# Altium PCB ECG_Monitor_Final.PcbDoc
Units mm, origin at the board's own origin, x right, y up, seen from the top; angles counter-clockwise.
Board outline 95 x 87 mm, 2 copper layers (Top Layer, Bottom Layer); 59 components, 41 nets, 158 pads, 2 vias.
Unrouted connection lines stored in the file: 17.
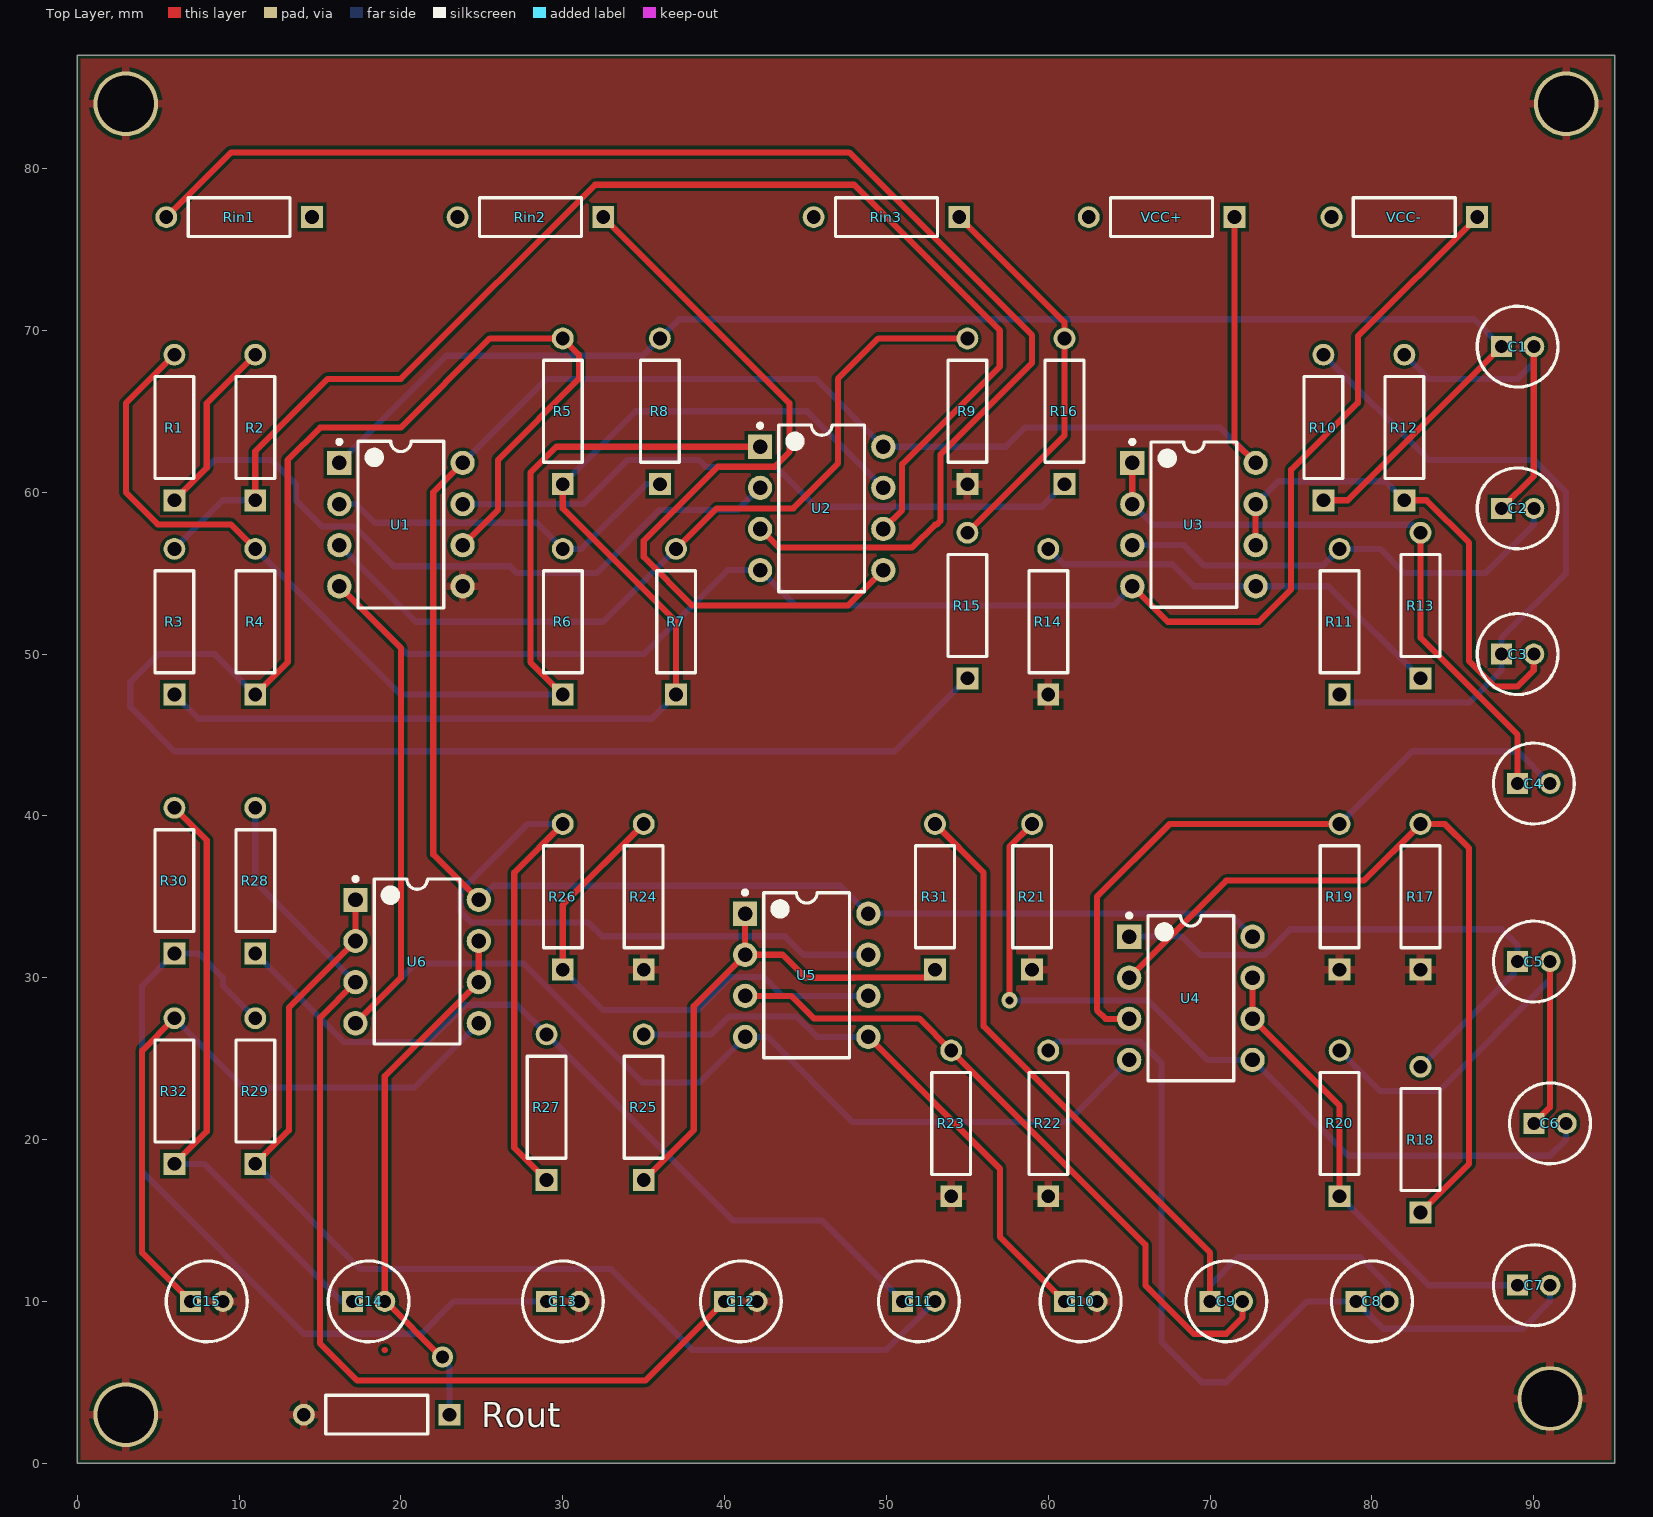
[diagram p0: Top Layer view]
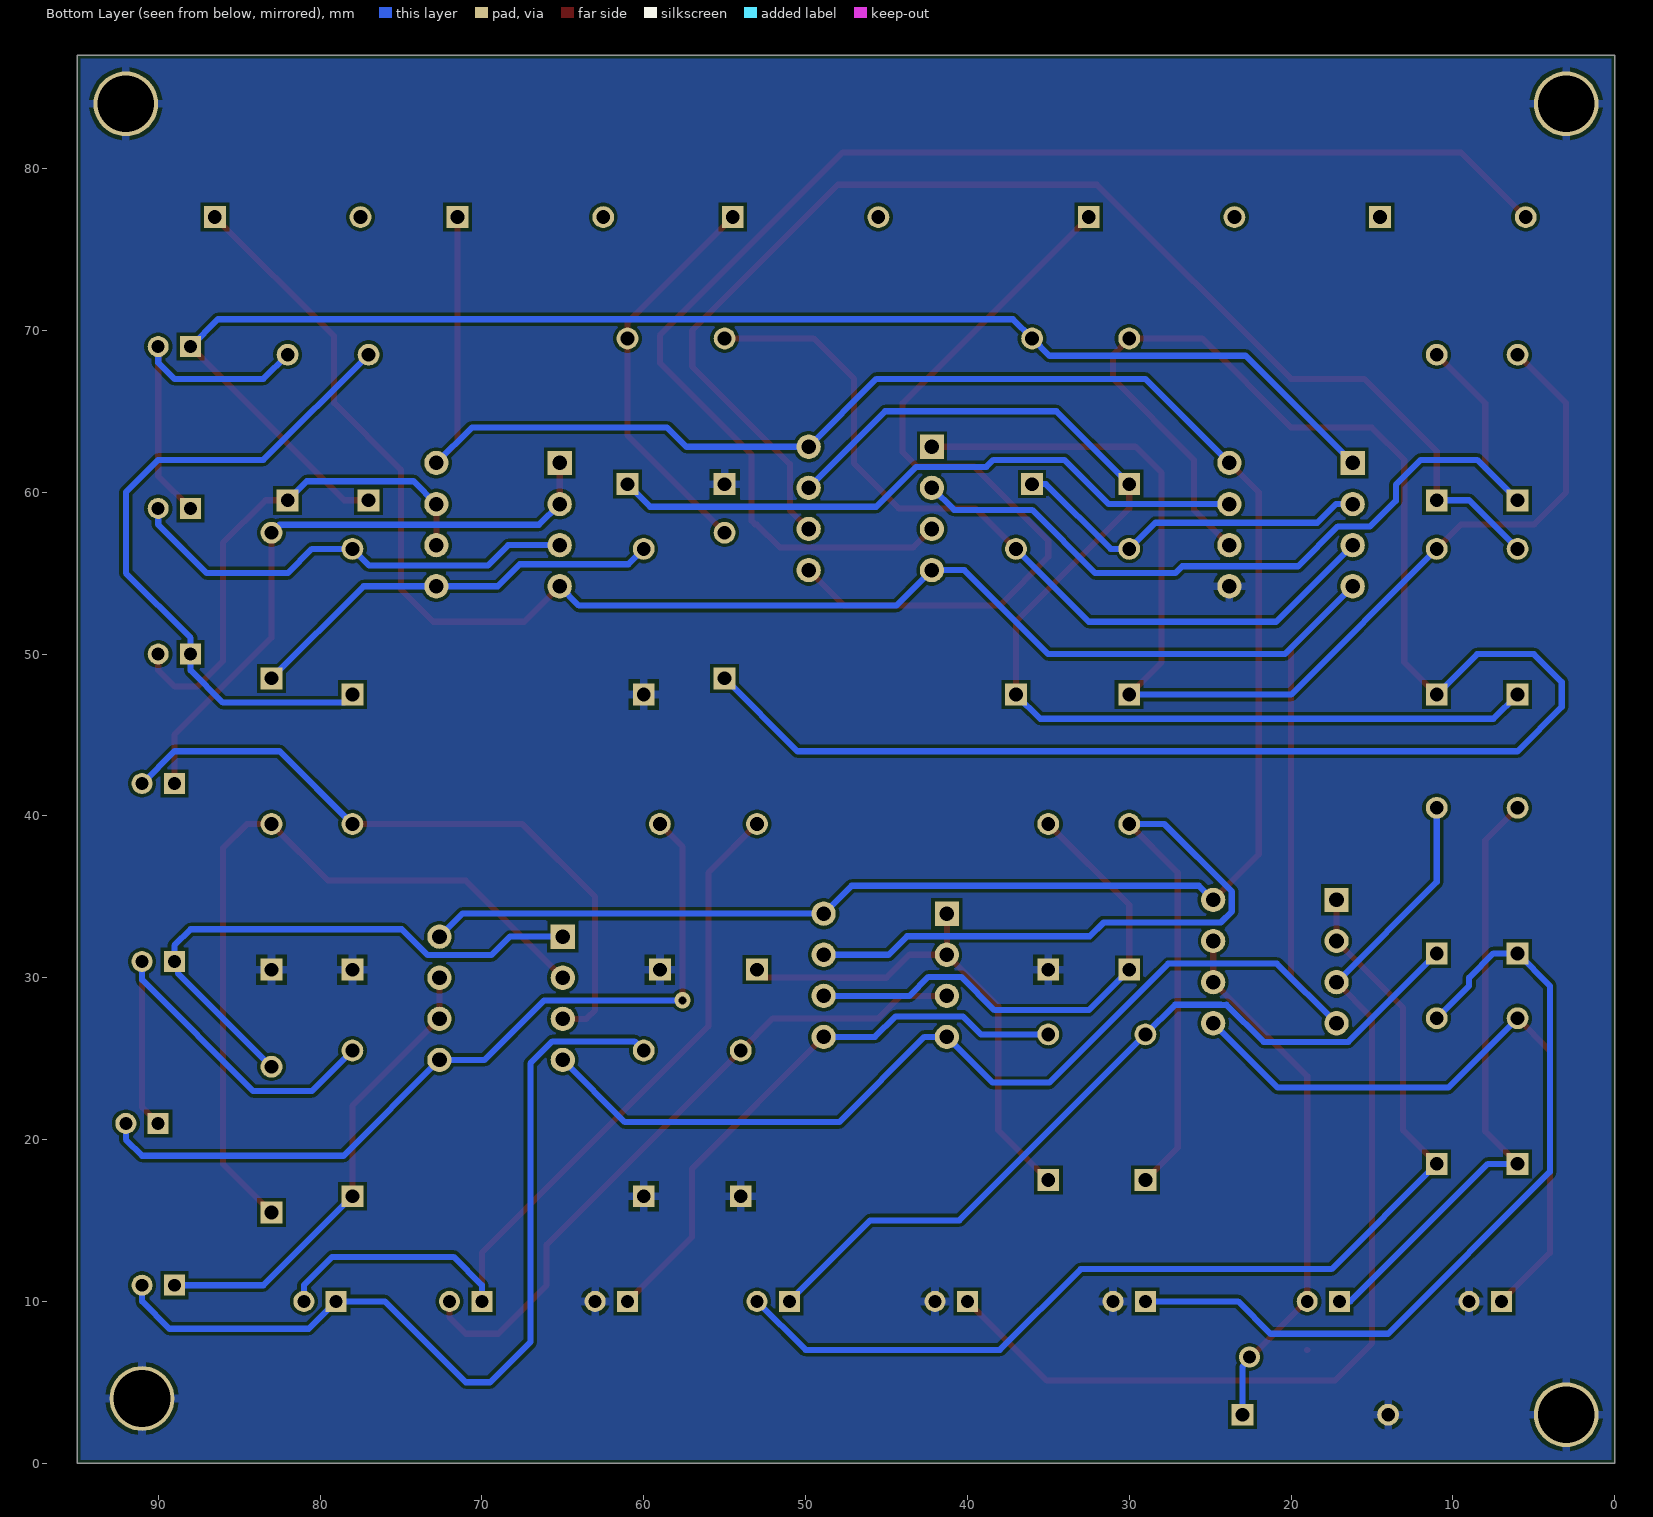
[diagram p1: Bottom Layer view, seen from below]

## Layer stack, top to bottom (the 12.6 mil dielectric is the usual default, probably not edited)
Top Solder: solder mask 0.0102, Solder Resist, Dk 3.5
Top Layer: signal copper 0.0356
Dielectric 1: dielectric 0.32, FR-4, Dk 4.8
Bottom Layer: signal copper 0.0356
Bottom Solder: solder mask 0.0102, Solder Resist, Dk 3.5

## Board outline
0,0 95,0 95,87 0,87

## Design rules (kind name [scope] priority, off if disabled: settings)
BoardOutlineClearance [All] p1: gap=0.2 ignorepadtopadclearanceinfootprint=FALSE except(0.4: Arc-SplitBarrior Arc-SplitContinuation Track-SplitBarrior Track-SplitContinuation SMDPad-SplitBarrior SMDPad-SplitContinuation THPad-SplitBarrior THPad-SplitContinuation Via-SplitBarrior Via-SplitContinuation Fill-SplitBarrior Fill-SplitContinuation Poly-SplitBarrior Poly-SplitContinuation Region-SplitBarrior Region-SplitContinuation Text-SplitBarrior Text-SplitContinuation)
Clearance "Clearance Bottom Layer" [OnLayer('Bottom Layer')] p1: gap=0.203 ignorepadtopadclearanceinfootprint=TRUE except(0.254: Arc-Text Track-Text SMDPad-Text THPad-Text Via-Text Fill-Text Poly-Text Region-Text Text-Text)
Clearance "Clearance Top Layer" [OnLayer('Top Layer')] p2: gap=0.203 ignorepadtopadclearanceinfootprint=TRUE except(0.254: Arc-Text Track-Text SMDPad-Text THPad-Text Via-Text Fill-Text Poly-Text Region-Text Text-Text)
Clearance [All] p3: gap=0.2 ignorepadtopadclearanceinfootprint=FALSE except(0.089: Arc-Arc Arc-Track Arc-SMDPad Track-Track Track-SMDPad SMDPad-SMDPad; 0.127: Arc-Via Track-Via SMDPad-Via THPad-Via Via-Via; 0.254: Arc-Text Track-Text SMDPad-Text THPad-Text Via-Text Fill-Text Poly-Text Region-Text Text-Text)
HoleSize [All] p1: absolutevalues=TRUE maxlimit=6.3 minlimit=0.2 maxpercent=80.000 minpercent=20.000
MinimumAnnularRing [All] p1: minimumring=0.076
MinimumSolderMaskSliver [All] p1: minsoldermaskwidth=0.1
PolygonConnect PolygonConnect_1 [All] p1: thpad.connectstyle=Relief thpad.reliefconductorwidth=0.508 thpad.reliefentries=4 thpad.polygonreliefangle="90 Angle" thpad.airgapwidth=0.254 smdpad.connectstyle=Relief smdpad.reliefconductorwidth=0.508 smdpad.reliefentries=4 smdpad.polygonreliefangle="90 Angle" smdpad.airgapwidth=0.254 via.connectstyle=Direct via.reliefconductorwidth=0.508 via.reliefentries=4 via.polygonreliefangle="90 Angle" via.airgapwidth=0.254
RoutingCorners [All] p1: cornerstyle=Round minsetback=2.54 maxsetback=2.54
RoutingVias [All] p1: holewidth=0.5 width=1 viastyle="Through Hole" minholewidth=0.2 minwidth=0.45 maxholewidth=1 maxwidth=2
SilkToSilkClearance [All] p1: silktosilkclearance=0.1
SilkToSolderMaskClearance [IsPad] p1: minsilkscreentomaskgap=0.1 clearancetoexposedcopper=TRUE
SolderMaskExpansion [All] p1: expansion=0.102 istentingtop=FALSE
Width [All] p1: maxlimit=2.54 minlimit=0.089 preferedwidth=0.381
25 further rules are at their usual default settings.

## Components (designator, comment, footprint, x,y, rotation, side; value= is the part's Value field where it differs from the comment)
C1 "ECA1HM100" CAPPR55-200-1100X500X1200 89,69 r0 top
C2 "ECA1HM100" CAPPR55-200-1100X500X1200 89,59 r0 top
C3 "ECA1HM100" CAPPR55-200-1100X500X1200 89,50 r0 top
C4 "ECA1HM100" CAPPR55-200-1100X500X1200 90,42 r0 top
C5 "ECA1HM100" CAPPR55-200-1100X500X1200 90,31 r0 top
C6 "ECA1HM100" CAPPR55-200-1100X500X1200 91,21 r0 top
C7 "ECA1HM100" CAPPR55-200-1100X500X1200 90,11 r0 top
C8 "ECA1HM100" CAPPR55-200-1100X500X1200 80,10 r0 top
C9 "ECA1HM100" CAPPR55-200-1100X500X1200 71,10 r0 top
C10 "ECA1HM100" CAPPR55-200-1100X500X1200 62,10 r0 top
C11 "ECA1HM100" CAPPR55-200-1100X500X1200 52,10 r0 top
C12 "ECA1HM100" CAPPR55-200-1100X500X1200 41,10 r0 top
C13 "ECA1HM100" CAPPR55-200-1100X500X1200 30,10 r0 top
C14 "ECA1HM100" CAPPR55-200-1100X500X1200 18,10 r0 top
C15 "ECA1HM100" CAPPR55-200-1100X500X1200 8,10 r0 top
R1 "" RESA60-630X240 6,64 r90 top
R2 "" RESA60-630X240 11,64 r90 top
R3 "" RESA60-630X240 6,52 r90 top
R4 "" RESA60-630X240 11,52 r90 top
R5 "" RESA60-630X240 30,65 r90 top
R6 "" RESA60-630X240 30,52 r90 top
R7 "" RESA60-630X240 37,52 r90 top
R8 "" RESA60-630X240 36,65 r90 top
R9 "" RESA60-630X240 55,65 r90 top
R10 "" RESA60-630X240 77,64 r90 top
R11 "" RESA60-630X240 78,52 r90 top
R12 "" RESA60-630X240 82,64 r90 top
R13 "" RESA60-630X240 83,53 r90 top
R14 "" RESA60-630X240 60,52 r90 top
R15 "" RESA60-630X240 55,53 r90 top
R16 "" RESA60-630X240 61,65 r90 top
R17 "" RESA60-630X240 83,35 r90 top
R18 "" RESA60-630X240 83,20 r90 top
R19 "" RESA60-630X240 78,35 r90 top
R20 "" RESA60-630X240 78,21 r90 top
R21 "" RESA60-630X240 59,35 r90 top
R22 "" RESA60-630X240 60,21 r90 top
R23 "" RESA60-630X240 54,21 r90 top
R24 "" RESA60-630X240 35,35 r90 top
R25 "" RESA60-630X240 35,22 r90 top
R26 "" RESA60-630X240 30,35 r90 top
R27 "" RESA60-630X240 29,22 r90 top
R28 "" RESA60-630X240 11,36 r90 top
R29 "" RESA60-630X240 11,23 r90 top
R30 "" RESA60-630X240 6,36 r90 top
R31 "" RESA60-630X240 53,35 r90 top
R32 "" RESA60-630X240 6,23 r90 top
Rin1 "" RESA60-630X240 10,77 r180 top
Rin2 "" RESA60-630X240 28,77 r180 top
Rin3 "" RESA60-630X240 50,77 r180 top
Rout "" RESA60-630X240 18.5,3 r180 top
U1 "LM4562NA" N08E 20,58 r0 top
U2 "LM4562NA" N08E 46,59 r0 top
U3 "TL072CP" P0008A 69,58 r0 top
U4 "TL072CP" P0008A 68.81,28.73 r0 top
U5 "TL072CP" P0008A 45.074,30.151 r0 top
U6 "TL072CP" P0008A 21,31 r0 top
VCC+ "" RESA60-630X240 67,77 r180 top
VCC- "" RESA60-630X240 82,77 r180 top

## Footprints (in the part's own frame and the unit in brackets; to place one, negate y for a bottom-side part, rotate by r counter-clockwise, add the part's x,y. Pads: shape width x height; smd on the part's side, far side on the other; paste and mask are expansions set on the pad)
CAPPR55-200-1100X500X1200 [mm] "THD, 2-Leads, Dia 5mm, Body Length 11mm"
  rect 1.3x1.3 hole 0.8: 1(-1,0)
  round 1.3 hole 0.8: 2(1,0)
  silkscreen extent -2.5,-2.5 2.5,2.5, body extent -2.5,-2.5 2.5,2.5, height 12
N08E [mm] "DIP, 8-Pin, Row Spacing 7.62 mm, Pitch 2.54 mm"
  rect 1.5x1.5 hole 0.9: 1(-3.81,3.81)
  round 1.5 hole 0.9: 2(-3.81,1.27) 3(-3.81,-1.27) 4(-3.81,-3.81) 5(3.81,-3.81) 6(3.81,-1.27) 7(3.81,1.27) 8(3.81,3.81)
  silkscreen extent -3.93,-5.15 2.65,5.23, body extent -3.6,-5.15 3.6,5.15, height 5.33
P0008A [mm] "DIP, 8-Leads, Body 10.15x6.6mm, Pitch 2.54mm"
  rect 1.5x1.5 hole 0.9: 1(-3.81,3.81)
  round 1.5 hole 0.9: 2(-3.81,1.27) 3(-3.81,-1.27) 4(-3.81,-3.81) 5(3.81,-3.81) 6(3.81,-1.27) 7(3.81,1.27) 8(3.81,3.81)
  silkscreen extent -3.93,-5.1 2.65,5.23, body extent -3.95,-5.07 3.95,5.07, height 5.08
RESA60-630X240 [mm] "Axial Resistor, 2-Leads, Dia 2.4mm, Body Length 6.3mm"
  rect 1.35x1.35 hole 0.85: 1(-4.5,0)
  round 1.35 hole 0.85: 2(4.5,0)
  silkscreen extent -3.15,-1.2 3.15,1.2, body extent -3.15,-1.2 3.15,1.2, height 2.4

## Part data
C1 C2 C3 C4 C5 C6 C7 C8 C9 C10 C11 C12 C13 C14 C15: library part CMP-1665-00038-2, "Aluminum Electrolytic Capacitor, 10 uF, +/- 20%, 50 V, -40 to 85 degC, 2-Pin THD, RoHS, Bulk", Capacitance=10uF, Case/Package=Radial, Dielectric Material=Aluminium, Leakage Current=3uA, Manufacturer=Panasonic, Max Operating Temperature=85degC, Min Operating Temperature=-40degC, Package Description="2-Pin Radial Lead, Dia 5 mm, Height 12 mm", Package Quantity=200, Package Reference=CAPPR55-200-1100X500X1200, Ripple Current=65mA, Tolerance=20%, Voltage=50V
R1 R2 R3 R4 R5 R6 R7 R8 R9 R10 R11 R12 R13 R14 R15 R16 R17 R18 R19 R20 R21 R22 R23 R24 R25 R26 R27 R28 R29 R30 R31 R32 Rin1 Rin2 Rin3 Rout VCC+ VCC-: library part CMP-1659-00072-1, "Axial Resistor, 221 Ohm, +/- 1%, 250 mW, -55 to 155 degC, 2-Pin THD, RoHS, Bulk", Case\Package=QFN, Max Operating Temperature="85 degC", Max Supply Voltage="3.6 V", Min Operating Temperature="-40 degC", Min Supply Voltage="1.95 V", Nominal Supply Voltage="2.5 V", Package Quantity=1000
U1 U2: library part CMP-0057-00043-2, "Dual High Performance, High Fidelity Audio Operational Amplifier, 8-pin MDIP", Manufacturer="National Semiconductor", PackageTopMarking=NSUZXYTT*LM*4562NA, PowerWise=Y
U3 U4 U5 U6: library part CMP-0017-00950-2, "Dual Low-Noise JFET-Input General-Purpose Operational Amplifier, 7 to 36 V, 0 to 70 degC, 8-pin DIP (P8), Pb-Free (RoHS)", Manufacturer="Texas Instruments", Rating=Catalog, Total Supply Voltage(Max)(+5V is 5, +/-5V is 10)=36, Total Supply Voltage(Min)(+5V is 5, +/-5V is 10)=7

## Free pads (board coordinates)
  round 4 hole 3.5: 5(3,3) 6(3,84) 7(92,84) 8(91,4)

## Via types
v1: diameter 1.3, hole 0.8, Top Layer to Bottom Layer, 1 vias
v2: diameter 1, hole 0.5, Top Layer to Bottom Layer, 1 vias

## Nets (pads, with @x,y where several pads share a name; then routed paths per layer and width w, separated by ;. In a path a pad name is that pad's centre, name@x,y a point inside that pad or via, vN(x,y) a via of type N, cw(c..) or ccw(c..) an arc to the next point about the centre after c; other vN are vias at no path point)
GND: C10.2 C12.2 C13.2 C15.2 pad.5 pad.6 pad.7 pad.8 R9.1 R14.1 R17.1 R19.1 R21.1 R22.1 R23.1 R24.1 Rout.2 U1.5
NetC1_1: C1.1 R8.2 R10.1 U1.1 | length 91.1
  Top Layer w0.381: R10.1 78.5,59.5 C1.1
  Bottom Layer w0.381: U1.1 22.809,68.429 34.929,68.429 R8.2 37.189,70.689 86.311,70.689 C1.1
NetC1_2: C1.2 C2.1 R12.2 | length 20.9
  Top Layer w0.381: C2.1 90,61 C1.2
  Bottom Layer w0.381: R12.2 83.5,67 89,67 90,68 C1.2
NetC2_2: C2.2 R11.2 U3.3 | length 28.6
  Bottom Layer w0.381: U3.3 68.366,56.73 69.621,55.475 76.975,55.475 R11.2 80.5,56.5 82,55 87,55 90,58 C2.2
NetC3_1: C3.1 R10.2 R11.1 | length 42.2
  Bottom Layer w0.381: R10.2 83.5,62 90,62 92,60 92,55 88,51 C3.1 88,49 86,47 78.708,47 78.692,47.015 78.485,47.015 R11.1
NetC3_2: C3.2 R12.1 U3.6 U3.7 | length 31.3
  Top Layer w0.381: U3.6 U3.7 ; R12.1 83.366,59.5 86,56.866 86,49.567 87.567,48 89,48 90,49 C3.2
  Bottom Layer w0.381: U3.7 74.222,60.682 80.818,60.682 R12.1
NetC4_1: C4.1 R13.2 U3.1 U3.2 | length 39.1
  Top Layer w0.381: U3.2 U3.1 ; R13.2 83,51 89,45 C4.1
  Bottom Layer w0.381: U3.2 66.471,57.989 82.511,57.989 R13.2
NetC4_2: C4.2 R19.2 U4.3 | length 41.8
  Top Layer w0.381: U4.3 63.54,27.46 63,28 63,35 67.5,39.5 R19.2
  Bottom Layer w0.381: R19.2 82.5,44 89,44 C4.2
NetC5_1: C5.1 R18.2 U4.1 | length 35.5
  Bottom Layer w0.381: U4.1 68.263,32.54 69.406,31.396 73.345,31.396 74.949,33 88,33 89,32 C5.1 88.778,30.778 88.778,30.278 R18.2
NetC5_2: C5.2 C6.1 R20.2 | length 28.4
  Top Layer w0.381: C6.1 91,22 C5.2
  Bottom Layer w0.381: R20.2 80.5,23 84.126,23 91,29.874 C5.2
NetC6_2: C6.2 R21.2 U4.5 | length 51.3
  Top Layer w0.381: v2(57.596,28.604) 57.596,38.096 R21.2
  Bottom Layer w0.381: v2(57.596,28.604) 66.144,28.604 69.827,24.92 U4.5 78.54,19 91,19 92,20 C6.2
NetC7_1: C7.1 R20.1 U4.6 U4.7 | length 29
  Top Layer w0.381: U4.7 U4.6 78,22.08 R20.1
  Bottom Layer w0.381: R20.1 83.5,11 C7.1
NetC7_2: C7.2 C8.1 R22.2 | length 54.5
  Bottom Layer w0.381: R22.2 60.564,26.064 65.646,26.064 67,24.71 67,7.488 69.488,5 71,5 76,10 C8.1 80.693,8.307 89.307,8.307 91,10 C7.2
NetC8_2: C8.2 C9.1 R31.2 | length 51
  Top Layer w0.381: R31.2 56,36.5 56,27 70,13 C9.1
  Bottom Layer w0.381: C9.1 70,11 71.752,12.752 79.248,12.752 81,11 C8.2
NetC9_2: C9.2 R23.2 U5.3 | length 42.3
  Top Layer w0.381: U5.3 44.119,28.881 45.515,27.485 52.015,27.485 R23.2 66,13.5 66,11 69,8 71,8 72,9 C9.2
NetC10_1: C10.1 R25.2 U5.5 | length 36.2
  Top Layer w0.381: U5.5 57.012,18.213 57.012,13.988 C10.1
  Bottom Layer w0.381: R25.2 39.164,26.5 40.275,27.611 44.439,27.611 45.709,26.341 U5.5
NetC11_1: C11.1 R27.2 R28.1 | length 50.8
  Bottom Layer w0.381: R28.1 16.464,26.036 21.694,26.036 23.992,28.334 24.005,28.321 24.321,28.321 24.334,28.334 27.166,28.334 R27.2 40.5,15 46,15 C11.1
NetC11_2: C11.2 R29.1 U6.1 U6.2 | length 66.9
  Top Layer w0.381: R29.1 13.081,20.581 13.081,28.161 U6.2 U6.1
  Bottom Layer w0.381: R29.1 17.5,12 33,12 38,7 50,7 C11.2
NetC12_1: C12.1 R28.2 U6.3 | length 64.6
  Top Layer w0.381: U6.3 15,27.54 15,7.393 17.287,5.106 35.106,5.106 C12.1
  Bottom Layer w0.381: R28.2 11,35.92 U6.3
NetC13_1: C13.1 R29.2 R30.1 | length 51.2
  Bottom Layer w0.381: R29.2 9,29.5 9,30 7.5,31.5 R30.1 4,29.5 4,18 14,8 21.27,8 23.27,10 C13.1
NetC14_1: C14.1 R30.2 R32.1 | length 38.2
  Top Layer w0.381: R32.1 8,20.5 8,38.5 R30.2
  Bottom Layer w0.381: R32.1 7.837,18.5 16.337,10 C14.1
NetC14_2: C14.2 Rout.1 U6.6 U6.7 | length 33.4
  Top Layer w0.381: v1(22.568,6.563) 22.503,6.563 19.065,10 C14.2 19,17 19,23.92 U6.6 U6.7
  Bottom Layer w0.381: v1(22.568,6.563) 22.568,6.395 23,5.963 Rout.1
NetC15_1: C15.1 R32.2 U6.5 | length 41.8
  Top Layer w0.381: R32.2 4,25.5 4,13 C15.1
  Bottom Layer w0.381: R32.2 10.283,23.217 20.837,23.217 U6.5
NetR1_1: R1.1 R2.2 U2.2 | length 54
  Top Layer w0.381: R1.1 8,61.5 8,65.5 R2.2
  Bottom Layer w0.381: R1.1 8.5,62 12,62 13.523,60.477 13.523,59.477 15.112,57.888 17.109,57.888 19.565,55.431 26.721,55.431 27.152,55 32.096,55 36,58.904 40.824,58.904 U2.2
NetR1_2: R1.2 R4.2 R6.1 U2.1 | length 71.3
  Top Layer w0.381: R1.2 3,65.5 3,59.987 4.972,58.015 9.485,58.015 R4.2 ; R6.1 28,49.5 28,61.205 29.605,62.81 U2.1
  Bottom Layer w0.381: R4.2 20,47.5 R6.1
NetR2_1: R2.1 R3.2 U2.6 | length 81.1
  Top Layer w0.381: R2.1 11,62.536 15.464,67 20,67 32,79 48,79 57,70 57,67.764 50.967,61.731 50.967,58.887 U2.6
  Bottom Layer w0.381: R3.2 9,59.5 R2.1
NetR3_1: R3.1 R5.1 R7.1 U2.7 | length 71.8
  Top Layer w0.381: R5.1 30,59 37,52 R7.1
  Bottom Layer w0.381: R3.1 7.5,46 35.5,46 R7.1 ; R5.1 34.5,65 45.08,65 U2.7
NetR4_1: R4.1 R5.2 R15.1 U1.6 | length 117.3
  Top Layer w0.381: R4.1 13,49.5 13,62 15,64 20,64 25.5,69.5 R5.2 31,68.5 31,67 26,62 26,58.92 U1.6
  Bottom Layer w0.381: R4.1 8.5,50 5,50 3.269,48.269 3.269,46.731 6,44 50.5,44 R15.1
NetR6_2: R6.2 R8.1 U1.2 | length 22.6
  Bottom Layer w0.381: U1.2 17.232,59.27 18.386,58.116 28.384,58.116 R6.2 31.143,56.5 35.143,60.5 R8.1
NetR7_2: R7.2 R9.2 U1.3 | length 51.1
  Top Layer w0.381: R7.2 39.505,59.005 44.236,59.005 47,61.77 47,67 49.5,69.5 R9.2
  Bottom Layer w0.381: U1.3 20.92,52 32.5,52 R7.2
NetR13_1: R13.1 R14.2 U3.5 | length 26.3
  Bottom Layer w0.381: R14.2 60.949,55.551 67.655,55.551 69.016,54.19 U3.5 77.31,54.19 R13.1
NetR15_2: R15.2 R16.2 Rin3.1 | length 24.7
  Top Layer w0.381: Rin3.1 61,70.5 R16.2 ; R15.2 61,63.5 R16.2
NetR16_1: R16.1 U1.7 | length 40.1
  Bottom Layer w0.381: U1.7 31.27,59.27 34,62 38.392,62 38.823,61.569 43.166,61.569 45.628,59.107 59.607,59.107 R16.1
NetR17_2: R17.2 R18.1 U4.2 | length 49.3
  Top Layer w0.381: U4.2 71,36 79.5,36 R17.2 84.5,39.5 86,38 86,18.5 R18.1
NetR24_2: R24.2 R26.1 U5.6 | length 32.3
  Top Layer w0.381: R26.1 30,34.5 R24.2
  Bottom Layer w0.381: R26.1 32.5,28 38.326,28 40.375,30.049 42.407,30.049 43.575,28.881 U5.6
NetR25_1: R25.1 R31.1 U5.1 U5.2 | length 34.6
  Top Layer w0.381: R25.1 38.089,20.589 38.089,28.246 U5.2 ; U5.1 U5.2 ; 48,30.025 45.025,30.025 45,30 ; R31.1 52.525,30.025 48.025,30.025 48,30 45,30 ; U5.2 43.579,31.421 45,30
NetR26_2: R26.2 R27.1 U5.7 | length 59.7
  Top Layer w0.381: R27.1 27,19.5 27,36.5 R26.2
  Bottom Layer w0.381: R26.2 27.829,39.5 23.662,35.333 23.662,34.088 24.336,33.414 31.586,33.414 32.435,32.565 43.727,32.565 44.871,31.421 U5.7
NetRin1_2: Rin1.2 U2.3 | length 85.9
  Top Layer w0.381: Rin1.2 9.5,81 47.692,81 59,69.692 59,68 53.329,62.329 53.329,58.223 53.106,58 53,58 51.586,56.586 43.334,56.586 U2.3
NetRin2_1: Rin2.1 U2.5 | length 48.5
  Top Layer w0.381: Rin2.1 44,65.5 44,62.478 43.093,61.571 39.571,61.571 35,57 35,56 38,53 47.62,53 U2.5
NetU1_4: U1.4 U2.4 U3.4 U4.4 U5.4 U6.4 VCC-.1 | length 180.7
  Top Layer w0.381: U1.4 20,50.38 20,30 U6.4 ; U3.4 67.38,52 73,52 75,54 75,61.398 79.135,65.533 79.135,69.635 VCC-.1
  Bottom Layer w0.381: U1.4 20.38,50 35,50 40.19,55.19 U2.4 44.38,53 64,53 U3.4 ; U6.4 20.874,30.874 27.593,30.874 34.945,23.522 38.445,23.522 U5.4 42.659,26.341 47.917,21.083 61.163,21.083 U4.4
NetU1_8: U1.8 U2.8 U3.8 U4.8 U5.8 U6.8 VCC+.1 | length 148.4
  Top Layer w0.381: U1.8 22,60 22,37.62 U6.8 ; VCC+.1 71.5,63.12 U3.8
  Bottom Layer w0.381: U1.8 29,67 45.62,67 U2.8 57.362,62.81 58.552,64 70.62,64 U3.8 ; U6.8 25.689,35.689 47.156,35.689 U5.8 71.199,33.961 U4.8
pads on no net: Rin1.1 Rin2.2 Rin3.2 VCC+.2 VCC-.2

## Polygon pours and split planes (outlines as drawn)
GND on Top Layer "GND_L01_P000" (solid, pour order 0): 0,87 95,87 95,0 0,0
GND on Bottom Layer "GND_L02_P001" (solid, pour order 1): 0,87 95,87 95,0 0,0

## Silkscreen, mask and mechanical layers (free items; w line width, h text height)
Mechanical 1:
  the board outline again, w0.254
